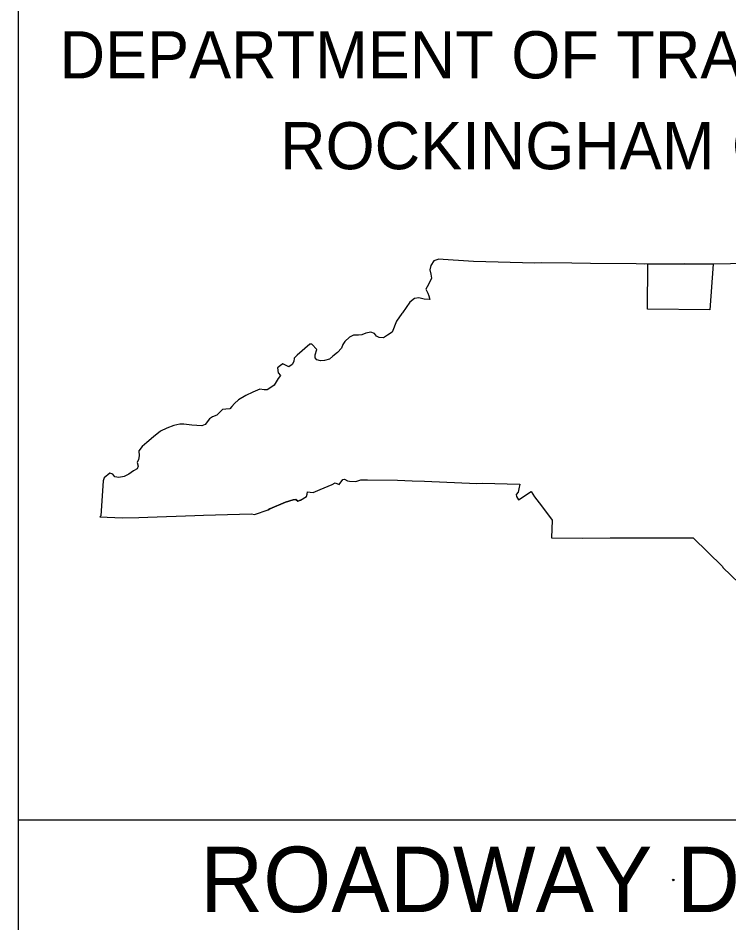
# Model space of a CAD drawing. Extents: x 1184048.9 to 1184122, y 1246638.9 to 1246660.6.
# Drawn here: x 1184112.785 to 1184113.861, y 1246657.819 to 1246659.188 of the extents above; entities that cross this region are included whole.
import ezdxf

# ---------------------------------------------------------------- set-up
doc = ezdxf.new("R2010")
doc.units = 0
for name, color, linetype in [('Old_Level_20', 7, 'Continuous'), ('P_RDY_Dimension_Text', 7, 'Continuous'), ('Sheet Plan CELL', 7, 'Continuous')]:
    doc.layers.add(name, color=color, linetype=linetype)

msp = doc.modelspace()

# ---------------------------------------------------------------- linework, layer by layer
at = {"layer": 'Old_Level_20'}
for points in [[(1184113.889, 1246658.8167), (1184113.8366, 1246658.8155), (1184113.7934, 1246658.8161), (1184113.7325, 1246658.8154), (1184113.7201, 1246658.8161), (1184113.6514, 1246658.8163), (1184113.6229, 1246658.8169), (1184113.5772, 1246658.8173), (1184113.5672, 1246658.8171), (1184113.4745, 1246658.8197), (1184113.421, 1246658.8232), (1184113.4203, 1246658.8225), (1184113.4145, 1246658.8203), (1184113.4097, 1246658.8135), (1184113.408, 1246658.807), (1184113.4096, 1246658.8005), (1184113.4107, 1246658.7941), (1184113.4061, 1246658.7849), (1184113.4024, 1246658.7778), (1184113.4052, 1246658.7717), (1184113.4068, 1246658.7674), (1184113.408, 1246658.7621), (1184113.3998, 1246658.7626), (1184113.3915, 1246658.7648), (1184113.385, 1246658.7634), (1184113.3782, 1246658.7581), (1184113.367, 1246658.7419), (1184113.366, 1246658.7409), (1184113.3579, 1246658.7295), (1184113.3515, 1246658.7124), (1184113.3441, 1246658.7079), (1184113.3381, 1246658.7041), (1184113.3315, 1246658.7047), (1184113.3276, 1246658.7065), (1184113.3248, 1246658.7104), (1184113.3188, 1246658.7125), (1184113.3112, 1246658.7113), (1184113.3054, 1246658.7088), (1184113.3004, 1246658.7083), (1184113.2929, 1246658.7081), (1184113.2868, 1246658.7051), (1184113.2796, 1246658.6984), (1184113.2766, 1246658.6942), (1184113.2745, 1246658.6885), (1184113.2684, 1246658.6817), (1184113.2617, 1246658.6763), (1184113.2565, 1246658.6718), (1184113.2491, 1246658.6697), (1184113.2427, 1246658.6692), (1184113.2374, 1246658.6709), (1184113.2348, 1246658.6739), (1184113.2348, 1246658.6785), (1184113.2371, 1246658.6863), (1184113.2296, 1246658.6943), (1184113.2269, 1246658.6946), (1184113.2076, 1246658.678), (1184113.2032, 1246658.6734), (1184113.2025, 1246658.6681), (1184113.1998, 1246658.6635), (1184113.195, 1246658.6603), (1184113.1859, 1246658.6649), (1184113.1826, 1246658.6623), (1184113.1778, 1246658.6589), (1184113.179, 1246658.6509), (1184113.1822, 1246658.6473), (1184113.1791, 1246658.6423), (1184113.173, 1246658.6325), (1184113.1691, 1246658.6297)], [(1184113.1691, 1246658.6297), (1184113.1623, 1246658.6256), (1184113.1576, 1246658.6256), (1184113.1509, 1246658.6264), (1184113.1405, 1246658.622), (1184113.1301, 1246658.6167), (1184113.1187, 1246658.6105), (1184113.1128, 1246658.6045), (1184113.109, 1246658.6001), (1184113.1056, 1246658.5967), (1184113.0995, 1246658.596), (1184113.0945, 1246658.5955), (1184113.0905, 1246658.5914), (1184113.0862, 1246658.5871), (1184113.0796, 1246658.5848), (1184113.0749, 1246658.5813), (1184113.0682, 1246658.573), (1184113.0633, 1246658.5708), (1184113.0482, 1246658.572), (1184113.0363, 1246658.5733), (1184113.0301, 1246658.5734), (1184113.0208, 1246658.5712), (1184113.0106, 1246658.5673), (1184113.0011, 1246658.5627), (1184112.9901, 1246658.5542), (1184112.9801, 1246658.5456), (1184112.9732, 1246658.5396), (1184112.9681, 1246658.533), (1184112.9684, 1246658.5257), (1184112.9678, 1246658.5201), (1184112.9654, 1246658.5153), (1184112.967, 1246658.5098), (1184112.9654, 1246658.5059), (1184112.9602, 1246658.503), (1184112.9532, 1246658.4979), (1184112.946, 1246658.4941), (1184112.9377, 1246658.4928), (1184112.9316, 1246658.494), (1184112.9288, 1246658.4978), (1184112.924, 1246658.4993), (1184112.9157, 1246658.4925), (1184112.9141, 1246658.4878), (1184112.9104, 1246658.4348), (1184112.9092, 1246658.4334), (1184112.9428, 1246658.432), (1184112.9682, 1246658.4325), (1184112.9815, 1246658.4327), (1184113.0526, 1246658.4353), (1184113.0657, 1246658.436), (1184113.1387, 1246658.438), (1184113.1432, 1246658.437), (1184113.1635, 1246658.444), (1184113.1664, 1246658.4455), (1184113.1898, 1246658.4553), (1184113.2016, 1246658.4589), (1184113.2058, 1246658.4595), (1184113.2087, 1246658.457), (1184113.2124, 1246658.4585), (1184113.2215, 1246658.464), (1184113.2225, 1246658.4677), (1184113.2232, 1246658.4711), (1184113.2272, 1246658.4706), (1184113.232, 1246658.4703), (1184113.2423, 1246658.4746), (1184113.2606, 1246658.482), (1184113.2651, 1246658.4847), (1184113.271, 1246658.4824), (1184113.2768, 1246658.4897), (1184113.2794, 1246658.4904), (1184113.2836, 1246658.4878), (1184113.2868, 1246658.4874), (1184113.2963, 1246658.4867), (1184113.3037, 1246658.4893), (1184113.3139, 1246658.4891), (1184113.3593, 1246658.4887), (1184113.3817, 1246658.4877), (1184113.4004, 1246658.4874), (1184113.4793, 1246658.4839), (1184113.4873, 1246658.4844), (1184113.5444, 1246658.4828), (1184113.5431, 1246658.4757), (1184113.5416, 1246658.4706), (1184113.5389, 1246658.4672), (1184113.5391, 1246658.4642), (1184113.5424, 1246658.459), (1184113.5613, 1246658.4714), (1184113.5667, 1246658.4636), (1184113.5772, 1246658.4498), (1184113.5934, 1246658.4283), (1184113.5925, 1246658.4017), (1184113.639, 1246658.401), (1184113.6808, 1246658.4016), (1184113.7605, 1246658.4013), (1184113.8031, 1246658.4016), (1184113.8063, 1246658.4014), (1184113.851, 1246658.3584), (1184113.8513, 1246658.3568), (1184113.9259, 1246658.285)], [(1184113.2124, 1246658.4585), (1184113.2087, 1246658.457), (1184113.2058, 1246658.4595), (1184113.2016, 1246658.4589), (1184113.1898, 1246658.4553), (1184113.1664, 1246658.4455), (1184113.1635, 1246658.444)]]:
    msp.add_lwpolyline(points, dxfattribs=at)
at = {"layer": 'P_RDY_Dimension_Text'}
msp.add_lwpolyline([(1184113.8319, 1246658.7462), (1184113.7373, 1246658.7474), (1184113.738, 1246658.8154), (1184113.7957, 1246658.8161), (1184113.8366, 1246658.8155)], close=True, dxfattribs=at)
at = {"layer": 'Sheet Plan CELL'}
for p, q in [((1184112.7855, 1246639.3047), (1184112.786, 1246660.1998)), ((1184114.7666, 1246657.9743), (1184112.786, 1246657.9743))]:
    msp.add_line(p, q, dxfattribs=at)
msp.add_circle((1184113.7764, 1246657.884), 0.00119, dxfattribs=at)

# ---------------------------------------------------------------- texts
for s, height, p in [('DEPARTMENT OF TRANSPORTATION', 0.071302, (1184112.8481, 1246659.0965)), ('ROCKINGHAM COUNTY', 0.071302, (1184113.1817, 1246658.959)), ('ROADWAY DESIGN ', 0.099032, (1184113.0606, 1246657.8354))]:
    msp.add_text(s, height=height, rotation=0, dxfattribs=at).set_placement(p)

doc.saveas('drawing.dxf')
